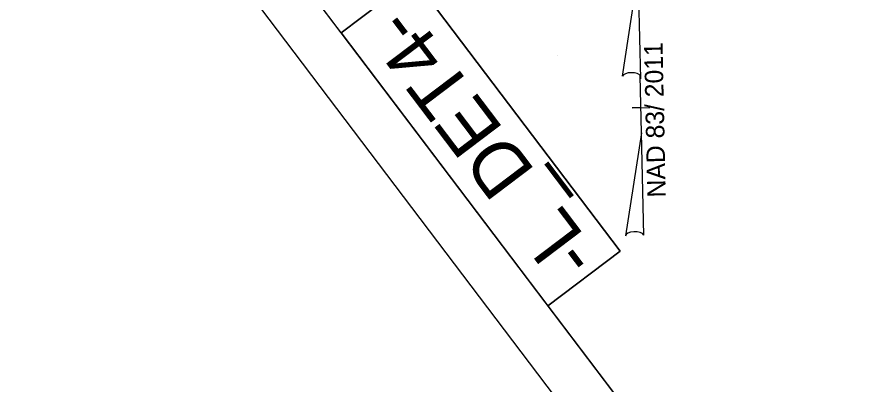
# Model space of a CAD drawing. Extents: x 475599 to 477488, y 499839 to 501843.
# Drawn here: x 475598.8 to 475990.7, y 500860.3 to 501029.5 of the extents above; entities that cross this region are included whole.
import ezdxf

# ---------------------------------------------------------------- set-up
doc = ezdxf.new("R2010")
doc.units = 0
for name, color, linetype in [('Old_Level_1', 7, 'Continuous'), ('Prop Grid Mask', 7, 'Continuous'), ('Prop North Arrow NAD83 for Plan Sheets CELL', 7, 'Continuous'), ('Sheet Layout Plan Border', 7, 'Continuous'), ('Sheet North Arrow Point CELL', 7, 'Continuous'), ('Sheet Plan CELL', 7, 'Continuous'), ('Sheet Plot Border Outside CELL', 7, 'Continuous')]:
    doc.layers.add(name, color=color, linetype=linetype)

msp = doc.modelspace()

# ---------------------------------------------------------------- linework, layer by layer
at = {"layer": 'Prop Grid Mask'}
msp.add_lwpolyline([(475747.69, 501022.15), (475842.67, 500896.68), (475875.92, 500921.85), (475780.95, 501047.33)], close=True, dxfattribs=at)
at = {"layer": 'Prop North Arrow NAD83 for Plan Sheets CELL'}
for p, q in [((475876.96, 501002.32), (475884.17, 501048.84)), ((475884.22, 501048.84), (475885.24, 501001.05)), ((475885.76, 500976.26), (475885.21, 501002.45)), ((475885.24, 501001.05), (475885.21, 501002.4)), ((475881.52, 500987.77), (475881.47, 500987.77)), ((475885.07, 500987.84), (475881.52, 500987.77)), ((475881.57, 500987.77), (475889.57, 500987.94)), ((475885.76, 500976.26), (475878.42, 500928.84)), ((475886.81, 500929.22), (475885.76, 500976.26))]:
    msp.add_line(p, q, dxfattribs=at)
for centre, start_param, end_param in [((475881.1, 501001.92), 0.216388, 2.908219), ((475882.66, 500928.76), 0.201328, 3.141593)]:
    msp.add_ellipse(centre, major_axis=(4.23, 0.06), ratio=0.461098, start_param=start_param, end_param=end_param, dxfattribs=at)
at = {"layer": 'Sheet Layout Plan Border'}
msp.add_lwpolyline([(477369.49, 500619.34), (476565.06, 501682.05), (476503.29, 501631.07), (476482.51, 501623.32), (476353.41, 501551.57), (476353.41, 501551.57), (475928.12, 501315.23), (475798.16, 501243.01), (475886.06, 501126.89), (475780.95, 501047.33), (475875.92, 500921.85), (475842.66, 500896.67), (476532.3, 499985.63)], close=True, dxfattribs=at)
at = {"layer": 'Sheet North Arrow Point CELL'}
msp.add_line((475846.92, 501011.89), (475846.92, 501011.89), dxfattribs=at)
at = {"layer": 'Sheet Plan CELL'}
for points in [[(475626.94, 501181.67), (476532.26, 499985.63), (477369.47, 500619.35), (476464.15, 501815.36)], [(477369.49, 500619.37), (476532.3, 499985.63), (475747.68, 501022.14), (475867.32, 501112.71), (475746.6, 501272.21), (476464.15, 501815.36)], [(475747.68, 501022.13), (475626.94, 501181.67), (475646.93, 501196.75), (475767.68, 501037.27)]]:
    msp.add_lwpolyline(points, close=True, dxfattribs=at)
at = {"layer": 'Sheet Plot Border Outside CELL'}
msp.add_lwpolyline([(476471.84, 501842.5), (477487.9, 500500.19), (476614.82, 499839.31), (475598.76, 501181.63)], close=True, dxfattribs=at)

# ---------------------------------------------------------------- texts
at = {"layer": 'Old_Level_1'}
msp.add_text('-L_DET4-', height=25, rotation=127.1236, dxfattribs=at).set_placement((475866.55, 500919.86))
at = {"layer": 'Prop North Arrow NAD83 for Plan Sheets CELL'}
msp.add_text('NAD 83/ 2011', height=8.5, rotation=91.2162, dxfattribs=at).set_placement((475896.92, 500946.57))

doc.saveas('drawing.dxf')
